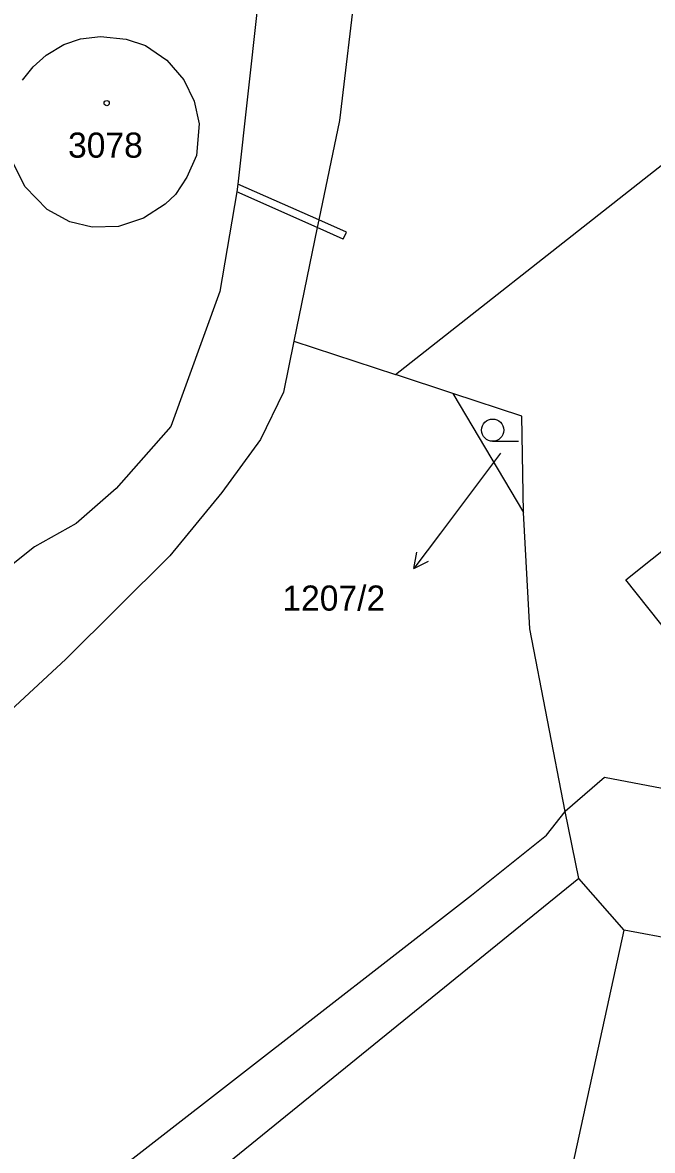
# Model space of a CAD drawing. Extents: x -679220 to -673243, y -1075091 to -1066557.
# Drawn here: x -676771.7 to -676729.1, y -1070747.8 to -1070671.5 of the extents above; entities that cross this region are included whole.
import ezdxf

# ---------------------------------------------------------------- set-up
doc = ezdxf.new("R2010")
doc.units = 0
for name, color, linetype in [('Hranice parcel', 7, 'Continuous'), ('Parcelní čísla', 7, 'Continuous'), ('Pop  PČ popisy', 7, 'Continuous'), ('Vnitřní kresba', 7, 'Continuous'), ('Značky budov', 7, 'Continuous'), ('Značky kultur', 7, 'Continuous')]:
    doc.layers.add(name, color=color, linetype=linetype)

msp = doc.modelspace()

# ---------------------------------------------------------------- linework, layer by layer
at = {"layer": 'Hranice parcel'}
for p, q in [((-676753.35, -1070693.05), (-676746.48, -1070695.31)), ((-676742.6, -1070696.58), (-676746.48, -1070695.31)), ((-676742.6, -1070696.58), (-676737.82, -1070704.65)), ((-676734.09, -1070729.39), (-676735.01, -1070724.87)), ((-676731.02, -1070732.9), (-676734.09, -1070729.39)), ((-676736.91, -1070759.79), (-676731.02, -1070732.9)), ((-676653.34, -1070747.37), (-676731.02, -1070732.9))]:
    msp.add_line(p, q, dxfattribs=at)
for points in [[(-676731.52, -1070568.42), (-676734.1, -1070581.2), (-676734.98, -1070588.22), (-676736.24, -1070595.32), (-676736.58, -1070597.25), (-676739.91, -1070616.1), (-676748.98, -1070657.15), (-676749.14, -1070658.34), (-676749.31, -1070659.68), (-676749.45, -1070660.75), (-676749.12, -1070668.45), (-676750.27, -1070678.12), (-676751.67, -1070684.85), (-676751.78, -1070685.37), (-676753.35, -1070693.05)], [(-676746.48, -1070695.31), (-676699.22, -1070658.08), (-676694.15, -1070652.24), (-676678.37, -1070639.47), (-676676.12, -1070636.08)], [(-676750.76, -1070636.36), (-676751.86, -1070641.87), (-676752.81, -1070646.73), (-676754.29, -1070657.14), (-676754.5, -1070658.58), (-676757.15, -1070682.42), (-676757.21, -1070682.95), (-676758.37, -1070689.69), (-676761.67, -1070698.83), (-676765.37, -1070703.02), (-676768.07, -1070705.38), (-676770.91, -1070706.97), (-676791.81, -1070723.66)], [(-676771.72, -1070675.39), (-676771, -1070674.49), (-676770.12, -1070673.7), (-676768.91, -1070672.99), (-676767.78, -1070672.59), (-676766.43, -1070672.44), (-676764.7, -1070672.62), (-676763.4, -1070673.05), (-676761.96, -1070674.04)], [(-676761.96, -1070674.04), (-676760.79, -1070675.38), (-676760.1, -1070676.81), (-676759.76, -1070678.35), (-676759.95, -1070680.5), (-676760.6, -1070681.95), (-676761.37, -1070683.13), (-676762.07, -1070683.78), (-676763.53, -1070684.74), (-676765.22, -1070685.3), (-676767, -1070685.33), (-676768.51, -1070684.97), (-676770.05, -1070684.15), (-676771.53, -1070682.62), (-676772.39, -1070680.92)], [(-676753.35, -1070693.05), (-676754.06, -1070696.49), (-676755.62, -1070699.7), (-676758.23, -1070703.29), (-676761.75, -1070707.57), (-676768.78, -1070714.55), (-676783.7, -1070728.39), (-676788.47, -1070731.18), (-676797.21, -1070738.47), (-676800.75, -1070744.01), (-676805.46, -1070747.13), (-676810.17, -1070748.61), (-676816.4, -1070753.01), (-676822.34, -1070756.86), (-676829.38, -1070760.64), (-676836.63, -1070765.94)], [(-676737.82, -1070704.65), (-676737.93, -1070698.12), (-676742.6, -1070696.58)], [(-676721.36, -1070718.86), (-676722.49, -1070719.76), (-676730.9, -1070709.2), (-676725.45, -1070704.85), (-676725.17, -1070705.2), (-676722.27, -1070702.9), (-676722.55, -1070702.55), (-676715.89, -1070697.27)], [(-676735.01, -1070724.87), (-676737.41, -1070712.51), (-676737.82, -1070704.65)], [(-676712.71, -1070726.3), (-676732.35, -1070722.57), (-676735.01, -1070724.87)], [(-676819.52, -1070791.34), (-676804.94, -1070779.94), (-676741.35, -1070730.52), (-676736.27, -1070726.47), (-676735.01, -1070724.87)], [(-676734.09, -1070729.39), (-676764.56, -1070754.12), (-676779.02, -1070765.48), (-676780.93, -1070766.95), (-676802.84, -1070783.93), (-676807.58, -1070787.57), (-676808.32, -1070787.51), (-676809.11, -1070788.09), (-676821.6, -1070800.12), (-676825.36, -1070804.84), (-676827.62, -1070809.91), (-676828.1, -1070816.09), (-676825.15, -1070823.23), (-676820.55, -1070832.07), (-676814.12, -1070843.75)]]:
    msp.add_lwpolyline(points, dxfattribs=at)
at = {"layer": 'Pop  PČ popisy'}
for p, q in [((-676739.38, -1070700.63), (-676743.44, -1070706.03)), ((-676743.44, -1070706.03), (-676745.246, -1070708.427)), ((-676745.246, -1070708.427), (-676745.043, -1070707.326)), ((-676745.246, -1070708.427), (-676744.243, -1070707.928))]:
    msp.add_line(p, q, dxfattribs=at)
at = {"layer": 'Vnitřní kresba'}
for p, q in [((-676751.67, -1070684.85), (-676757.15, -1070682.42)), ((-676751.78, -1070685.37), (-676757.21, -1070682.95)), ((-676749.8, -1070685.68), (-676751.67, -1070684.85)), ((-676750.02, -1070686.16), (-676751.78, -1070685.37)), ((-676750.02, -1070686.16), (-676749.8, -1070685.68))]:
    msp.add_line(p, q, dxfattribs=at)
at = {"layer": 'Značky budov'}
msp.add_circle((-676766.017, -1070676.949), 0.175, dxfattribs=at)
at = {"layer": 'Značky kultur'}
msp.add_line((-676739.913, -1070699.82), (-676738.163, -1070699.82), dxfattribs=at)
msp.add_circle((-676739.913, -1070699.07), 0.75, dxfattribs=at)

# ---------------------------------------------------------------- texts
at = {"layer": 'Parcelní čísla'}
for s, p in [('3078', (-676768.63, -1070680.64)), ('1207/2', (-676754.135, -1070711.278))]:
    msp.add_text(s, height=1.7, dxfattribs=at).set_placement(p)

doc.saveas('drawing.dxf')
